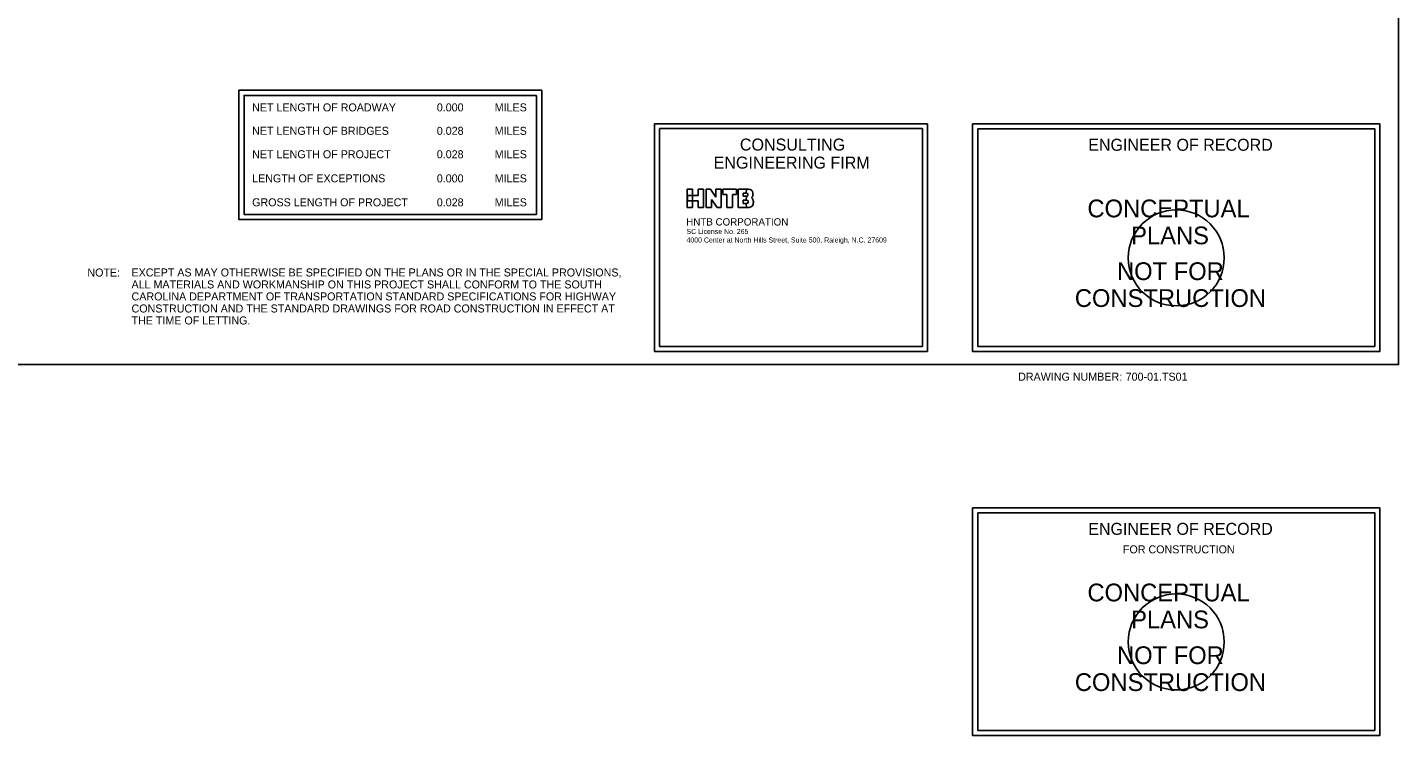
# Model space of a CAD drawing. Extents: x -4.82 to 4.15, y -0.44 to 2.32.
# Drawn here: x 1.007 to 2.792, y -0.442 to 0.48 of the extents above; entities that cross this region are included whole.
import ezdxf

# ---------------------------------------------------------------- set-up
doc = ezdxf.new("R2010")
doc.units = 0
for name, color, linetype in [('BR_BORDER LINES', 7, 'Continuous'), ('BR_DETAILS', 7, 'Continuous'), ('BR_TEXT', 7, 'Continuous'), ('Default', 7, 'Continuous'), ('NoPlot', 7, 'Continuous'), ('V7_23', 7, 'Continuous')]:
    doc.layers.add(name, color=color, linetype=linetype)

msp = doc.modelspace()

# ---------------------------------------------------------------- linework, layer by layer
at = {"layer": 'BR_BORDER LINES'}
msp.add_lwpolyline([(0.1667, 1.7917), (2.7917, 1.7917), (2.7917, 0.0417), (0.1667, 0.0417)], close=True, dxfattribs=at)
at = {"layer": 'BR_DETAILS'}
for p, q in [((1.8232, 0.3551), (2.1782, 0.3551)), ((1.8232, 0.0584), (1.8232, 0.3551)), ((1.8296, 0.3487), (2.1718, 0.3487)), ((1.8296, 0.0648), (1.8296, 0.3487)), ((2.1718, 0.3487), (2.1718, 0.0648)), ((2.1782, 0.3551), (2.1782, 0.0584)), ((2.1782, 0.0584), (1.8232, 0.0584)), ((2.1718, 0.0648), (1.8296, 0.0648))]:
    msp.add_line(p, q, dxfattribs=at)
for points in [[(2.2372, 0.3551), (2.7672, 0.3551), (2.7672, 0.0584), (2.2372, 0.0584)], [(2.2439, 0.3485), (2.7606, 0.3485), (2.7606, 0.0651), (2.2439, 0.0651)], [(2.2372, -0.1449), (2.7672, -0.1449), (2.7672, -0.4415), (2.2372, -0.4415)], [(2.2439, -0.1515), (2.7606, -0.1515), (2.7606, -0.4349), (2.2439, -0.4349)]]:
    msp.add_lwpolyline(points, close=True, dxfattribs=at)
at = {"layer": 'BR_TEXT'}
for points in [[(1.6763, 0.3987), (1.282, 0.3987), (1.282, 0.2303), (1.6763, 0.2303)], [(1.6696, 0.392), (1.2887, 0.392), (1.2887, 0.237), (1.6696, 0.237)]]:
    msp.add_lwpolyline(points, close=True, dxfattribs=at)
at = {"layer": 'NoPlot'}
for p, q in [((2.5022, 0.1804), (2.5022, 0.1804)), ((2.5022, -0.3196), (2.5022, -0.3196))]:
    msp.add_line(p, q, dxfattribs=at)
for centre in [(2.5022, 0.1804), (2.5022, -0.3196)]:
    msp.add_circle(centre, 0.0625, dxfattribs=at)
at = {"layer": 'V7_23'}
for p, q in [((1.8655, 0.2458), (1.8655, 0.2698)), ((1.8655, 0.2698), (1.8726, 0.2698)), ((1.8726, 0.2698), (1.8726, 0.2617)), ((1.8797, 0.2617), (1.8797, 0.2698)), ((1.8797, 0.2698), (1.8868, 0.2698)), ((1.8868, 0.2698), (1.8868, 0.2458)), ((1.8959, 0.2698), (1.8901, 0.2698)), ((1.8901, 0.2698), (1.8901, 0.2458)), ((1.903, 0.2593), (1.8959, 0.2698)), ((1.91, 0.2698), (1.903, 0.2698)), ((1.903, 0.2698), (1.903, 0.2593)), ((1.91, 0.2458), (1.91, 0.2698)), ((1.912, 0.2698), (1.912, 0.2629)), ((1.9297, 0.2698), (1.912, 0.2698)), ((1.9297, 0.2629), (1.9297, 0.2698)), ((1.9429, 0.2698), (1.9318, 0.2698)), ((1.9318, 0.2698), (1.9318, 0.2458)), ((1.9425, 0.2645), (1.9429, 0.2698)), ((1.9429, 0.2698), (1.9425, 0.2645)), ((1.8726, 0.2617), (1.8658, 0.2617)), ((1.8658, 0.2617), (1.8658, 0.2546)), ((1.8658, 0.2546), (1.8726, 0.2546)), ((1.8726, 0.2546), (1.8726, 0.2617)), ((1.8726, 0.2617), (1.8797, 0.2617)), ((1.8797, 0.2546), (1.8726, 0.2546)), ((1.8726, 0.2546), (1.8726, 0.2458)), ((1.8797, 0.2458), (1.8797, 0.2546)), ((1.8971, 0.2458), (1.8971, 0.2566)), ((1.8971, 0.2566), (1.9044, 0.2458)), ((1.912, 0.2629), (1.9173, 0.2629)), ((1.9173, 0.2629), (1.9173, 0.2458)), ((1.9244, 0.2458), (1.9244, 0.2629)), ((1.9244, 0.2629), (1.9297, 0.2629)), ((1.9384, 0.2609), (1.9384, 0.2645)), ((1.9384, 0.2645), (1.9425, 0.2645)), ((1.9427, 0.2609), (1.9384, 0.2609)), ((1.9384, 0.2512), (1.9384, 0.2556)), ((1.9384, 0.2556), (1.9424, 0.2556)), ((1.9425, 0.2512), (1.9384, 0.2512)), ((1.9424, 0.2556), (1.9427, 0.2609)), ((1.9427, 0.2609), (1.9424, 0.2556)), ((1.9428, 0.2458), (1.9425, 0.2512)), ((1.9425, 0.2512), (1.9428, 0.2458)), ((1.8726, 0.2458), (1.8655, 0.2458)), ((1.8868, 0.2458), (1.8797, 0.2458)), ((1.8901, 0.2458), (1.8971, 0.2458)), ((1.9044, 0.2458), (1.91, 0.2458)), ((1.9173, 0.2458), (1.9244, 0.2458)), ((1.9318, 0.2458), (1.9428, 0.2458))]:
    msp.add_line(p, q, dxfattribs=at)
for points in [[(1.9491, 0.2588), (1.9504, 0.2599), (1.951, 0.2616), (1.951, 0.2628), (1.951, 0.2671), (1.9479, 0.2698), (1.9429, 0.2698), (1.9429, 0.2698), (1.9429, 0.2698), (1.9429, 0.2698)], [(1.9424, 0.2556), (1.9446, 0.2556), (1.945, 0.2544), (1.945, 0.2534), (1.945, 0.252), (1.9441, 0.2512), (1.9425, 0.2512)], [(1.9425, 0.2645), (1.9444, 0.2645), (1.9446, 0.2632), (1.9446, 0.2627), (1.9446, 0.2621), (1.9442, 0.2609), (1.9427, 0.2609)], [(1.9428, 0.2458), (1.9483, 0.2458), (1.9517, 0.2489), (1.9517, 0.2539), (1.9517, 0.2558), (1.9507, 0.2577), (1.9491, 0.2588)]]:
    msp.add_open_spline(points, degree=3, dxfattribs=at)

# ---------------------------------------------------------------- texts
at = {"layer": 'BR_DETAILS'}
for s, height, p in [('CONCEPTUAL', 0.02311, (2.3866, 0.2332)), ('PLANS', 0.02311, (2.4435, 0.1981)), ('NOT FOR', 0.02311, (2.4251, 0.1515)), ('CONSTRUCTION', 0.023108, (2.3702, 0.1165)), ('CONCEPTUAL', 0.02311, (2.3866, -0.2668)), ('PLANS', 0.02311, (2.4435, -0.3019)), ('NOT FOR', 0.02311, (2.4251, -0.3485)), ('CONSTRUCTION', 0.023108, (2.3702, -0.3835))]:
    msp.add_text(s, height=height, rotation=360, dxfattribs=at).set_placement(p)
at = {"layer": 'BR_TEXT'}
for s, height, p in [('CONSULTING', 0.01563, (1.9342, 0.3201)), ('ENGINEERING FIRM', 0.015625, (1.9, 0.2966))]:
    msp.add_text(s, height=height, rotation=0, dxfattribs=at).set_placement(p)
for s, height, p in [('HNTB CORPORATION', 0.009516, (1.8643, 0.2225)), ('SC License No. 265', 0.006558, (1.8647, 0.2115)), ('4000 Center at North Hills Street, Suite 500, Raleigh, N.C. 27609', 0.006558, (1.8647, 0.2004))]:
    msp.add_text(s, height=height, dxfattribs=at).set_placement(p)
at = {"layer": 'Default'}
for s, height, p in [('NET LENGTH OF ROADWAY', 0.010417, (1.2992, 0.3711)), ('0.000', 0.01042, (1.5396, 0.3711)), ('MILES', 0.01042, (1.615, 0.3711)), ('NET LENGTH OF BRIDGES', 0.010417, (1.2992, 0.3406)), ('0.028', 0.01042, (1.5396, 0.3406)), ('MILES', 0.01042, (1.615, 0.3406)), ('ENGINEER OF RECORD', 0.015625, (2.3876, 0.3198)), ('NET LENGTH OF PROJECT', 0.010417, (1.2992, 0.3101)), ('0.028', 0.01042, (1.5396, 0.3101)), ('MILES', 0.01042, (1.615, 0.3101)), ('LENGTH OF EXCEPTIONS', 0.010417, (1.2992, 0.2787)), ('0.000', 0.01042, (1.5396, 0.2787)), ('MILES', 0.01042, (1.615, 0.2787)), ('GROSS LENGTH OF PROJECT', 0.010417, (1.2992, 0.2475)), ('0.028', 0.01042, (1.5396, 0.2475)), ('MILES', 0.01042, (1.615, 0.2475)), ('NOTE:', 0.01042, (1.0847, 0.1561)), ('EXCEPT AS MAY OTHERWISE BE SPECIFIED ON THE PLANS OR IN THE SPECIAL PROVISIONS, ', 0.010417, (1.1422, 0.1562)), ('ALL MATERIALS AND WORKMANSHIP ON THIS PROJECT SHALL CONFORM TO THE SOUTH ', 0.010417, (1.1422, 0.1406)), ('CAROLINA DEPARTMENT OF TRANSPORTATION STANDARD SPECIFICATIONS FOR HIGHWAY ', 0.010417, (1.1422, 0.125)), ('CONSTRUCTION AND THE STANDARD DRAWINGS FOR ROAD CONSTRUCTION IN EFFECT AT ', 0.010417, (1.1422, 0.1093)), ('THE TIME OF LETTING.', 0.010417, (1.1422, 0.0937)), ('DRAWING NUMBER:', 0.010417, (2.2964, 0.0205)), ('700-01.TS01', 0.010417, (2.4364, 0.0205)), ('ENGINEER OF RECORD', 0.015625, (2.3876, -0.1802)), ('FOR CONSTRUCTION', 0.010417, (2.4328, -0.2043))]:
    msp.add_text(s, height=height, dxfattribs=at).set_placement(p)

doc.saveas('drawing.dxf')
